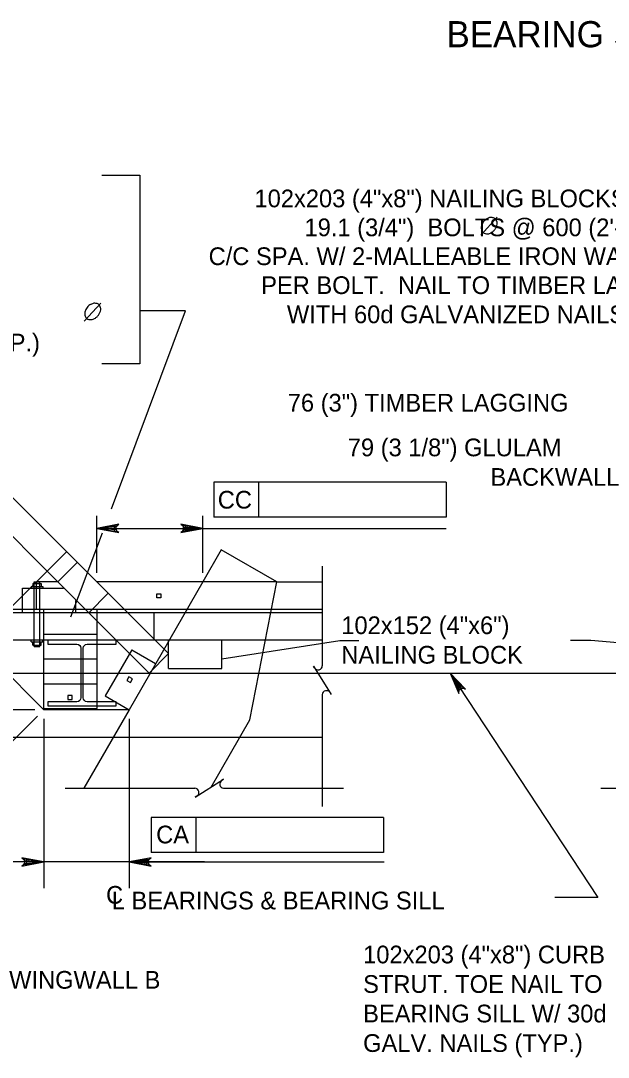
# Model space of a CAD drawing. Extents: x 635440 to 640306, y 296653 to 298484.
# Drawn here: x 639831.5 to 639931, y 296904.9 to 297080.4 of the extents above; entities that cross this region are included whole.
import ezdxf

# ---------------------------------------------------------------- set-up
doc = ezdxf.new("R2010")
doc.units = 0
for name, color, linetype in [('3', 7, 'Continuous'), ('4', 7, 'Continuous'), ('5', 7, 'Continuous'), ('8', 7, 'Continuous')]:
    doc.layers.add(name, color=color, linetype=linetype)

# ---------------------------------------------------------------- blocks, each defined once
blk = doc.blocks.new('HPILE')
at = {"layer": '3'}
for p, q in [((-0.12, -2.66), (-0.12, 2.66)), ((0.12, 2.66), (0.12, -2.66)), ((-3.67, -3.1), (-0.56, -3.1))]:
    blk.add_line(p, q, dxfattribs=at)
for points in [[(-0.56, 3.1), (-3.67, 3.1), (-3.67, 3.54), (3.67, 3.54), (3.67, 3.1), (0.56, 3.1)], [(0.56, -3.1), (3.67, -3.1), (3.67, -3.54), (-3.67, -3.54), (-3.67, -3.1)]]:
    blk.add_lwpolyline(points, dxfattribs=at)
for centre, start, end in [((-0.56, 2.66), 0, 90), ((0.56, 2.66), 90, 180), ((-0.56, -2.66), 270, 0), ((0.56, -2.66), 180, 270)]:
    blk.add_arc(centre, 0.438, start, end, dxfattribs=at)

msp = doc.modelspace()

# ---------------------------------------------------------------- linework, layer by layer
at = {"layer": '3'}
for p, q in [((639844.34, 296985.39), (639814.81, 297014.91)), ((639835.95, 296987.2), (639811.52, 297011.63)), ((639835.37, 296963.73), (639799.5, 296999.6)), ((639839.24, 296990.49), (639823.92, 296975.18)), ((639865.45, 296990.81), (639862.31, 296985.39)), ((639874.84, 296985.39), (639865.45, 296990.81)), ((639841.05, 296988.67), (639837.77, 296985.39)), ((639853.21, 296969.94), (639835.95, 296987.2)), ((639833.5, 296985.12), (639833.5, 296984.59)), ((639833.5, 296985.12), (639834.95, 296985.12)), ((639833.76, 296985.39), (639834.68, 296985.39)), ((639833.76, 296974.41), (639833.76, 296985.39)), ((639834.13, 296980.73), (639834.13, 296985.39)), ((639837.77, 296985.39), (639834.13, 296985.39)), ((639834.68, 296974.41), (639834.68, 296985.39)), ((639834.95, 296985.12), (639834.95, 296984.59)), ((639862.31, 296985.39), (639844.34, 296985.39)), ((639856.5, 296973.23), (639844.34, 296985.39)), ((639862.31, 296985.39), (639849.81, 296963.73)), ((639874.84, 296985.39), (639862.31, 296985.39)), ((639870.29, 296961.99), (639874.84, 296985.39)), ((639874.84, 296985.39), (639882.56, 296985.39)), ((639831.76, 296980.11), (639831.76, 296984.33)), ((639831.76, 296984.33), (639838.69, 296984.33)), ((639833.23, 296984.59), (639833.23, 296984.33)), ((639833.23, 296984.59), (639835.21, 296984.59)), ((639835.21, 296984.59), (639835.21, 296984.33)), ((639846.27, 296983.45), (639842.99, 296980.16)), ((639840.78, 296980.11), (639840.78, 296982.24)), ((639821.1, 296980.73), (639882.56, 296980.73)), ((639882.56, 296980.16), (639821.1, 296980.16)), ((639835.37, 296963.92), (639835.37, 296980.73)), ((639844.39, 296963.92), (639844.39, 296980.73)), ((639854.08, 296975.51), (639854.08, 296980.16)), ((639835.37, 296976.53), (639844.39, 296976.53)), ((639882.56, 296975.51), (639821.1, 296975.51)), ((639833.23, 296975.2), (639833.23, 296975.46)), ((639833.23, 296975.2), (639835.21, 296975.2)), ((639833.5, 296974.67), (639833.5, 296975.2)), ((639833.5, 296974.67), (639834.95, 296974.67)), ((639834.95, 296974.67), (639834.95, 296975.2)), ((639835.21, 296975.2), (639835.21, 296975.46)), ((639856.49, 296970.7), (639856.49, 296975.51)), ((639865.52, 296970.7), (639865.52, 296975.51)), ((639833.76, 296974.41), (639834.68, 296974.41)), ((639850.29, 296973.87), (639845.78, 296966.06)), ((639850.29, 296973.87), (639854.32, 296971.54)), ((639856.5, 296973.23), (639853.21, 296969.94)), ((639835.37, 296972.33), (639844.39, 296972.33)), ((639808.13, 296969.94), (640028.07, 296969.94)), ((639856.49, 296970.7), (639865.52, 296970.7)), ((639835.37, 296968.13), (639844.39, 296968.13)), ((639845.78, 296966.06), (639849.81, 296963.73)), ((639835.37, 296963.92), (639844.39, 296963.92)), ((639849.81, 296963.73), (639835.37, 296963.73)), ((639849.81, 296963.73), (639842.14, 296950.44)), ((639863.72, 296950.63), (639870.29, 296961.99)), ((639821.1, 296959.08), (639847.13, 296959.08))]:
    msp.add_line(p, q, dxfattribs=at)
for points in [[(639855.2, 296982.65), (639854.5, 296982.65), (639854.5, 296983.35), (639855.2, 296983.35)], [(639849.8, 296969.28), (639849.45, 296968.67), (639850.06, 296968.33), (639850.41, 296968.93)], [(639839.47, 296965.45), (639840.16, 296965.45), (639840.16, 296966.15), (639839.47, 296966.15)]]:
    msp.add_lwpolyline(points, close=True, dxfattribs=at)
at = {"layer": '4'}
for p, q in [((639845.18, 297054.25), (639851.65, 297054.25)), ((639851.65, 297054.25), (639851.65, 297022.3)), ((639851.65, 297022.3), (639845.18, 297022.3)), ((639903.55, 297002.24), (639864.18, 297002.24)), ((639864.18, 297002.24), (639864.18, 296996.33)), ((639871.74, 297002.24), (639871.74, 296996.33)), ((639903.55, 297002.24), (639903.55, 296996.33)), ((639844.34, 296986.92), (639844.34, 296996.54)), ((639862.31, 296986.92), (639862.31, 296996.54)), ((639903.55, 296996.33), (639864.18, 296996.33)), ((639844.34, 296994.43), (639903.55, 296994.43)), ((639833.83, 296963.73), (639796.62, 296963.73)), ((639834.28, 296962.64), (639808.94, 296937.3)), ((639835.37, 296962.19), (639835.37, 296933.51)), ((639849.81, 296962.19), (639849.81, 296933.51)), ((639847.13, 296959.08), (639882.56, 296959.08)), ((639892.92, 296945.47), (639853.55, 296945.47)), ((639853.55, 296945.47), (639853.55, 296939.56)), ((639861.11, 296945.47), (639861.11, 296939.56)), ((639892.92, 296945.47), (639892.92, 296939.56)), ((639892.92, 296939.56), (639853.55, 296939.56)), ((639835.37, 296937.94), (639829.47, 296937.94)), ((639862.6, 296937.94), (639835.37, 296937.94)), ((639849.81, 296937.94), (639893.05, 296937.94))]:
    msp.add_line(p, q, dxfattribs=at)
for points in [[(639846.82, 296997.74), (639859.38, 297031.3), (639851.65, 297031.3)], [(639844.34, 296994.43), (639848.07, 296993.73), (639847.78, 296993.93), (639847.64, 296994.18), (639847.59, 296994.43), (639847.64, 296994.68), (639847.78, 296994.93), (639848.07, 296995.13), (639844.34, 296994.43), (639847.78, 296994.93), (639847.64, 296994.68), (639844.34, 296994.43), (639847.59, 296994.43), (639847.64, 296994.18), (639844.34, 296994.43), (639847.78, 296993.93)], [(639862.31, 296994.43), (639858.58, 296995.13), (639858.87, 296994.93), (639859.02, 296994.68), (639859.06, 296994.43), (639859.02, 296994.18), (639858.87, 296993.93), (639858.58, 296993.73), (639862.31, 296994.43), (639858.87, 296993.93), (639859.02, 296994.18), (639862.31, 296994.43), (639859.06, 296994.43), (639859.02, 296994.68), (639862.31, 296994.43), (639858.87, 296994.93)], [(639839.98, 296979.46), (639845.31, 296993.69)], [(639865.52, 296972.34), (639885.52, 296975.47), (639888.74, 296975.47)], [(639970.39, 296971.79), (639928.06, 296975.47), (639924.63, 296975.47)], [(639904.21, 296969.94), (639929.27, 296931.91), (639921.94, 296931.91)], [(639904.21, 296969.94), (639905.68, 296966.45), (639905.69, 296966.8), (639905.82, 296967.06), (639906, 296967.23), (639906.23, 296967.33), (639906.52, 296967.35), (639906.85, 296967.22), (639904.21, 296969.94), (639906.52, 296967.35), (639906.23, 296967.33), (639904.21, 296969.94), (639906, 296967.23), (639905.82, 296967.06), (639904.21, 296969.94), (639905.69, 296966.8)], [(639835.37, 296937.94), (639831.64, 296938.64), (639831.93, 296938.44), (639832.08, 296938.19), (639832.12, 296937.94), (639832.08, 296937.69), (639831.93, 296937.44), (639831.64, 296937.24), (639835.37, 296937.94), (639831.93, 296937.44), (639832.08, 296937.69), (639835.37, 296937.94), (639832.12, 296937.94), (639832.08, 296938.19), (639835.37, 296937.94), (639831.93, 296938.44)], [(639849.81, 296937.94), (639853.54, 296937.24), (639853.25, 296937.44), (639853.11, 296937.69), (639853.06, 296937.94), (639853.11, 296938.19), (639853.25, 296938.44), (639853.54, 296938.64), (639849.81, 296937.94), (639853.25, 296938.44), (639853.11, 296938.19), (639849.81, 296937.94), (639853.06, 296937.94), (639853.11, 296937.69), (639849.81, 296937.94), (639853.25, 296937.44)]]:
    msp.add_lwpolyline(points, dxfattribs=at)
for points in [[(639847.29, 296994.92), (639847.29, 296993.93), (639844.34, 296994.43)], [(639859.36, 296994.92), (639859.36, 296993.93), (639862.31, 296994.43)], [(639904.21, 296969.94), (639906.04, 296967.61), (639905.63, 296967.34)], [(639832.42, 296938.44), (639832.42, 296937.45), (639835.37, 296937.94)], [(639852.76, 296938.44), (639852.76, 296937.45), (639849.81, 296937.94)]]:
    msp.add_lwpolyline(points, close=True, dxfattribs=at)
at = {"layer": '5'}
for p, q in [((639909.41, 297044.07), (639912.21, 297047.13)), ((639842.23, 297029.54), (639845.03, 297032.6))]:
    msp.add_line(p, q, dxfattribs=at)
for points in [[(639911.92, 297046.83), (639911.7, 297047), (639911.48, 297047.06), (639911.21, 297047.09), (639911.05, 297047.09), (639910.78, 297047.02), (639910.54, 297046.91), (639910.36, 297046.81), (639910.03, 297046.55), (639909.77, 297046.21), (639909.62, 297045.89), (639909.52, 297045.6), (639909.5, 297045.34), (639909.52, 297045.1), (639909.64, 297044.78), (639909.76, 297044.6), (639910, 297044.42), (639910.36, 297044.34), (639910.77, 297044.35), (639911.29, 297044.59), (639911.67, 297044.91), (639911.96, 297045.31), (639912.15, 297045.73), (639912.21, 297046.19), (639912.13, 297046.48), (639911.93, 297046.83)], [(639844.74, 297032.3), (639844.52, 297032.47), (639844.3, 297032.53), (639844.03, 297032.56), (639843.87, 297032.56), (639843.6, 297032.49), (639843.35, 297032.38), (639843.18, 297032.28), (639842.85, 297032.02), (639842.59, 297031.68), (639842.44, 297031.36), (639842.34, 297031.07), (639842.32, 297030.81), (639842.34, 297030.57), (639842.46, 297030.25), (639842.58, 297030.07), (639842.82, 297029.89), (639843.18, 297029.81), (639843.59, 297029.82), (639844.11, 297030.06), (639844.49, 297030.38), (639844.78, 297030.78), (639844.97, 297031.2), (639845.03, 297031.66), (639844.95, 297031.95), (639844.75, 297032.3)]]:
    msp.add_spline(points, degree=3, dxfattribs=at)
at = {"layer": '8'}
for p, q in [((639882.56, 296988.05), (639882.56, 296971.17)), ((639882.56, 296966.31), (639882.56, 296947.35)), ((639838.97, 296950.44), (639860.96, 296950.44)), ((639865.82, 296950.44), (639886.18, 296950.44)), ((639929.73, 296950.44), (639942.99, 296950.44))]:
    msp.add_line(p, q, dxfattribs=at)
for points in [[(639881.24, 296970.81), (639881.05, 296971.11), (639884.07, 296966.3), (639883.87, 296966.62)], [(639861.32, 296949.11), (639861.02, 296948.92), (639865.83, 296951.95), (639865.51, 296951.74)]]:
    msp.add_lwpolyline(points, dxfattribs=at)
for centre, start, end in [((639881.85, 296971.17), 210, 0), ((639883.27, 296966.24), 32.1328, 174.6714), ((639865.89, 296951.14), 122.1328, 264.6714), ((639860.96, 296949.72), 300, 90)]:
    msp.add_arc(centre, 0.71, start, end, dxfattribs=at)

# ---------------------------------------------------------------- block references
at = {"layer": '3', "xscale": 1.57487212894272, "yscale": -1.57487212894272, "rotation": 180}
msp.add_blockref('HPILE', (639841.85, 296969.95), dxfattribs=at)

# ---------------------------------------------------------------- texts
at = {"layer": '4'}
for s, height, p in [('BEARING SILL SPLICE DETAILS', 4.4294, (639903.6, 297075.92)), ('CC', 3, (639864.85, 296997.79)), ('CA', 3, (639854.41, 296941.09)), ('C', 3, (639845.92, 296930.87)), ('L BEARINGS & BEARING SILL', 3.0001, (639846.88, 296929.91)), ('WINGWALL B', 3, (639829.5, 296916.48))]:
    msp.add_text(s, height=height, dxfattribs=at).set_placement(p)
at = {"layer": '5'}
for s, height, p in [('102x203 (4"x8") NAILING BLOCKS.  ', 3.0001, (639871.07, 297048.82)), ('19.1 (3/4")  BOLTS @ 600 (2\'-0")', 3.0001, (639879.55, 297043.92)), ('C/C SPA. W/ 2-MALLEABLE IRON WASHERS', 3.0001, (639863.3, 297039.03)), ('PER BOLT.  NAIL TO TIMBER LAGGING', 3.0001, (639872.2, 297034.13)), ('WITH 60d GALVANIZED NAILS (TYP.)', 3.0001, (639876.57, 297029.19)), ('PILOT HOLE. (TYP.)', 3.0001, (639797.27, 297024.4)), ('76 (3") TIMBER LAGGING', 3.0001, (639876.71, 297014.22)), ('79 (3 1/8") GLULAM', 3.0001, (639886.88, 297006.65)), ('BACKWALL', 3, (639911.05, 297001.65)), ('102x152 (4"x6")', 3.0001, (639885.78, 296976.53)), ('NAILING BLOCK', 3.0001, (639885.78, 296971.53)), ('102x203 (4"x8") CURB', 3.0001, (639889.48, 296920.77)), ('STRUT. TOE NAIL TO', 3.0001, (639889.48, 296915.77)), ('BEARING SILL W/ 30d', 3.0001, (639889.48, 296910.77)), ('GALV. NAILS (TYP.)', 3.0001, (639889.48, 296905.77))]:
    msp.add_text(s, height=height, dxfattribs=at).set_placement(p)

doc.saveas('drawing.dxf')
